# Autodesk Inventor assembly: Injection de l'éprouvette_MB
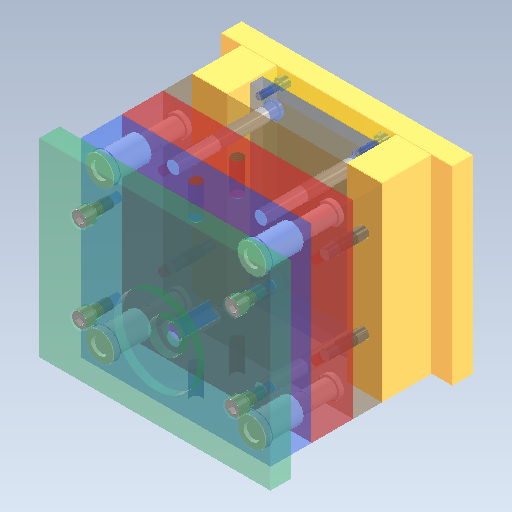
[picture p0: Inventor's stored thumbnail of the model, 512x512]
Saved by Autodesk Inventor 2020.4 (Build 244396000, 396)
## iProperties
Created: 2021-10
Part Number: Injection de l'éprouvette_MB
Document SubType Name: Assembly
Designer: mel
Author: mel
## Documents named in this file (16)
- D:\travail\année 2020-2021\itec\prépa injection plastique eduscol\dossier de travail\Ensemble des pièces de l'activité\Conception de moule1\Mo\FUTABA_SA-S 3\Injection de l'éprouvette_MB.iam
- C:\Users\mel\Documents\Inventor\Content Center Files\R2020\fr-FR\JIS 1176\JIS 1176 M8x25.ipt
- C:\Users\mel\Documents\Inventor\Content Center Files\R2020\fr-FR\GBA\M-GBA 20x49.ipt
- D:\travail\année 2020-2021\itec\prépa injection plastique eduscol\dossier de travail\Ensemble des pièces de l'activité\Conception de moule1\Mo\FUTABA_SA-S 3\Injection de l'éprouvette_MB_SA-SB1.ipt
- D:\travail\année 2020-2021\itec\prépa injection plastique eduscol\dossier de travail\Ensemble des pièces de l'activité\Conception de moule1\Mo\FUTABA_SA-S 3\Injection de l'éprouvette_MB_SA-SB2.ipt
- D:\travail\année 2020-2021\itec\prépa injection plastique eduscol\dossier de travail\Ensemble des pièces de l'activité\Conception de moule1\Mo\FUTABA_SA-S 3\Injection de l'éprouvette_MB_SA-EP.ipt
- C:\Users\mel\Documents\Inventor\Content Center Files\R2020\fr-FR\GPA\M-GPA20x97x39.ipt
- D:\travail\année 2020-2021\itec\prépa injection plastique eduscol\dossier de travail\Ensemble des pièces de l'activité\Conception de moule1\Mo\FUTABA_SA-S 3\Injection de l'éprouvette_MB_SA-ERP.ipt
- D:\travail\année 2020-2021\itec\prépa injection plastique eduscol\dossier de travail\Ensemble des pièces de l'activité\Conception de moule1\Mo\FUTABA_SA-S 3\Injection de l'éprouvette_MB_SA-BCP.ipt
- C:\Users\mel\Documents\Inventor\Content Center Files\R2020\fr-FR\JIS 1176\JIS 1176 M12x25.ipt
- D:\travail\année 2020-2021\itec\prépa injection plastique eduscol\dossier de travail\Ensemble des pièces de l'activité\Conception de moule1\Mo\FUTABA_SA-S 3\Injection de l'éprouvette_MB_RPN.ipt
- D:\travail\année 2020-2021\itec\prépa injection plastique eduscol\dossier de travail\Ensemble des pièces de l'activité\Conception de moule1\Mo\FUTABA_SA-S 3\Injection de l'éprouvette_MB_SA-S-AP.ipt
- D:\travail\année 2020-2021\itec\prépa injection plastique eduscol\dossier de travail\Ensemble des pièces de l'activité\Conception de moule1\Mo\FUTABA_SA-S 3\Injection de l'éprouvette_MB_SA-S-BP.ipt
- D:\travail\année 2020-2021\itec\prépa injection plastique eduscol\dossier de travail\Ensemble des pièces de l'activité\Conception de moule1\Mo\FUTABA_SA-S 3\Injection de l'éprouvette_MB_SA-TCP.ipt
- D:\travail\année 2020-2021\itec\prépa injection plastique eduscol\dossier de travail\Ensemble des pièces de l'activité\Conception de moule1\Mo\FUTABA_SA-S 3\Injection de l'éprouvette_MB_SA-SP.ipt
- C:\Users\mel\Documents\Inventor\Content Center Files\R2020\fr-FR\JIS 1176\JIS 1176 M12x120.ipt
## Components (33 placed, 15 different names)
1. Injection de l'éprouvette_MB_SA-SB1:1 — Affleurement:1, Affleurement:3, Placage:1, Placage:5
2. Injection de l'éprouvette_MB_SA-SB2:2 — Affleurement:2, Affleurement:4, Placage:2, Placage:6
3. Injection de l'éprouvette_MB_SA-EP:1 — Logement:1, Affleurement:5, Affleurement:6, Ejection, Placage:4
4. Injection de l'éprouvette_MB_SA-ERP:1 — Logement:7, Affleurement:7, Affleurement:8, Placage:4
5. Injection de l'éprouvette_MB_SA-BCP:1 — Logement:8, Ejection, Affleurement:9, Affleurement:10, Placage:5, Placage:6
6. Injection de l'éprouvette_MB_SA-S-AP:1 — Logement:2, Logement:5, Affleurement:11, Affleurement:12, Placage:7, PL1, Affleurement:19
7. Injection de l'éprouvette_MB_SA-S-BP:1 — Logement:3, Logement:4, Affleurement:13, Affleurement:14, PL1, Placage:9
8. Injection de l'éprouvette_MB_SA-TCP:1 — Logement:6, Placage:7, Affleurement:15, Affleurement:16
9. Injection de l'éprouvette_MB_SA-SP:1 — Placage:1, Placage:2, Affleurement:17, Affleurement:18, Placage:9
10. GPA 20x97x39:1 — Logement:3
11. GPA 20x97x39:3
12. JIS 1176 M12x25:1 — Logement:6
13. JIS 1176 M12x25:2
14. JIS 1176 M12x25:3
15. JIS 1176 M12x25:4
16. JIS 1176 M8x25:1 — Logement:1
17. JIS 1176 M8x25:2
18. JIS 1176 M8x25:3
19. JIS 1176 M8x25:4
20. JIS 1176 M12x120:1 — Logement:8
21. JIS 1176 M12x120:2
22. JIS 1176 M12x120:3
23. JIS 1176 M12x120:4
24. GBA 20x49:1 — Logement:2
25. GBA 20x49:3
26. GPA 20x97x39:2 — Logement:4
27. GPA 20x97x39:4
28. Injection de l'éprouvette_MB_RPN:1 — Logement:7
29. Injection de l'éprouvette_MB_RPN:2
30. Injection de l'éprouvette_MB_RPN:3
31. Injection de l'éprouvette_MB_RPN:4
32. GBA 20x49:2 — Logement:5
33. GBA 20x49:4
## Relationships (36: Flush 19, Mate 9, Insert 8)
- Logement:1 [Insert]: Injection de l'éprouvette_MB_SA-EP:1 ↔ JIS 1176 M8x25:1
- Logement:2 [Insert]: Injection de l'éprouvette_MB_SA-S-AP:1 ↔ GBA 20x49:1
- Logement:3 [Insert]: Injection de l'éprouvette_MB_SA-S-BP:1 ↔ GPA 20x97x39:1
- Logement:4 [Insert]: Injection de l'éprouvette_MB_SA-S-BP:1 ↔ GPA 20x97x39:2
- Logement:5 [Insert]: Injection de l'éprouvette_MB_SA-S-AP:1 ↔ GBA 20x49:2
- Logement:6 [Insert]: Injection de l'éprouvette_MB_SA-TCP:1 ↔ JIS 1176 M12x25:1
- Logement:7 [Insert]: Injection de l'éprouvette_MB_SA-ERP:1 ↔ Injection de l'éprouvette_MB_RPN:1
- Logement:8 [Insert]: Injection de l'éprouvette_MB_SA-BCP:1 ↔ JIS 1176 M12x120:1
- Affleurement:1 [Flush]: Injection de l'éprouvette_MB_SA-SB1:1
- Affleurement:2 [Flush]: Injection de l'éprouvette_MB_SA-SB2:2
- Affleurement:3 [Flush]: Injection de l'éprouvette_MB_SA-SB1:1
- Affleurement:4 [Flush]: Injection de l'éprouvette_MB_SA-SB2:2
- Placage:1 [Mate]: Injection de l'éprouvette_MB_SA-SB1:1 ↔ Injection de l'éprouvette_MB_SA-SP:1
- Placage:2 [Mate]: Injection de l'éprouvette_MB_SA-SB2:2 ↔ Injection de l'éprouvette_MB_SA-SP:1
- Affleurement:5 [Flush]: Injection de l'éprouvette_MB_SA-EP:1
- Affleurement:6 [Flush]: Injection de l'éprouvette_MB_SA-EP:1
- Ejection [Mate]: Injection de l'éprouvette_MB_SA-EP:1 ↔ Injection de l'éprouvette_MB_SA-BCP:1
- Affleurement:7 [Flush]: Injection de l'éprouvette_MB_SA-ERP:1
- Affleurement:8 [Flush]: Injection de l'éprouvette_MB_SA-ERP:1
- Placage:4 [Mate]: Injection de l'éprouvette_MB_SA-EP:1 ↔ Injection de l'éprouvette_MB_SA-ERP:1
- Affleurement:9 [Flush]: Injection de l'éprouvette_MB_SA-BCP:1
- Affleurement:10 [Flush]: Injection de l'éprouvette_MB_SA-BCP:1
- Placage:5 [Mate]: Injection de l'éprouvette_MB_SA-SB1:1 ↔ Injection de l'éprouvette_MB_SA-BCP:1
- Placage:6 [Mate]: Injection de l'éprouvette_MB_SA-SB2:2 ↔ Injection de l'éprouvette_MB_SA-BCP:1
- Affleurement:11 [Flush]: Injection de l'éprouvette_MB_SA-S-AP:1
- Affleurement:12 [Flush]: Injection de l'éprouvette_MB_SA-S-AP:1
- Placage:7 [Mate]: Injection de l'éprouvette_MB_SA-S-AP:1 ↔ Injection de l'éprouvette_MB_SA-TCP:1
- Affleurement:13 [Flush]: Injection de l'éprouvette_MB_SA-S-BP:1
- Affleurement:14 [Flush]: Injection de l'éprouvette_MB_SA-S-BP:1
- PL1 [Mate]: Injection de l'éprouvette_MB_SA-S-AP:1 ↔ Injection de l'éprouvette_MB_SA-S-BP:1
- Affleurement:15 [Flush]: Injection de l'éprouvette_MB_SA-TCP:1
- Affleurement:16 [Flush]: Injection de l'éprouvette_MB_SA-TCP:1
- Affleurement:17 [Flush]: Injection de l'éprouvette_MB_SA-SP:1
- Affleurement:18 [Flush]: Injection de l'éprouvette_MB_SA-SP:1
- Placage:9 [Mate]: Injection de l'éprouvette_MB_SA-S-BP:1 ↔ Injection de l'éprouvette_MB_SA-SP:1
- Affleurement:19 [Flush]: Injection de l'éprouvette_MB_SA-S-AP:1
